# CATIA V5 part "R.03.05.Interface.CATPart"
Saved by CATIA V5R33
Part number: R.03.05.Interface
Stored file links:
  C:\Users\Ryzen5700u\Desktop\robot_cicloidale_singolo\Assieme_robot_cicloidale_singolo\R.03.05.Interface.CATPart

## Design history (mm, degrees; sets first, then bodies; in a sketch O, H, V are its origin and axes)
Body1 "Solid1" (main body)
  Solid1: solid without history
